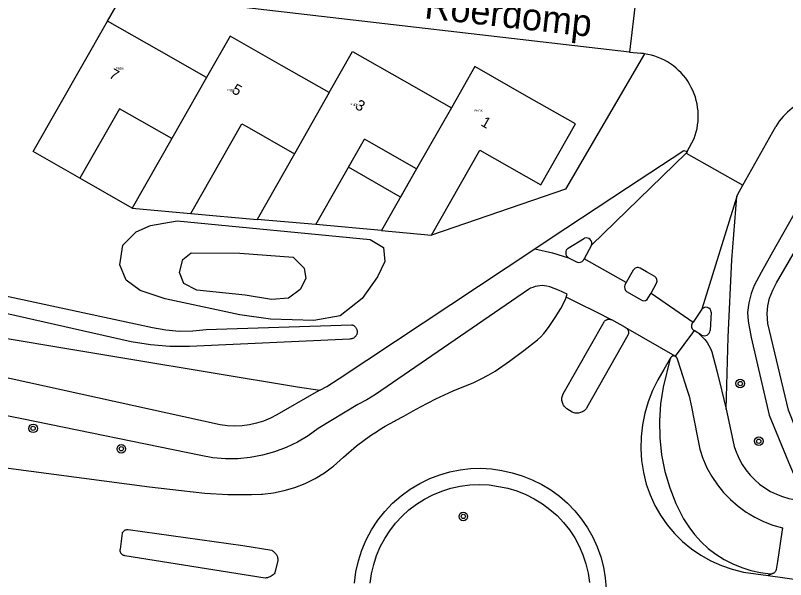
# Model space of a CAD drawing. Extents: x 131000 to 133013, y 393000 to 396501.
# Drawn here: x 131784.2 to 131855.9, y 393446.7 to 393499.2 of the extents above; entities that cross this region are included whole.
import ezdxf

# ---------------------------------------------------------------- set-up
doc = ezdxf.new("R2010")
doc.units = 0
for name, color, linetype in [('gg-anno-huisnummerreeks BGT', 7, 'Continuous'), ('gg-anno-openbare ruimte label', 7, 'Continuous'), ('gg-bbg-luifel en loopbrug', 7, 'Continuous'), ('gt-symb-boom', 7, 'Continuous'), ('gx-grn-maaiveld', 7, 'Continuous'), ('kenmerkpunt-x pandkandidaat', 7, 'Continuous')]:
    doc.layers.add(name, color=color, linetype=linetype)

# ---------------------------------------------------------------- blocks, each defined once
blk = doc.blocks.new('gt0-BOOM')
at = {"layer": 'gt-symb-boom'}
for radius in [0.4, 0.2]:
    blk.add_circle((0, 0), radius, dxfattribs=at)

msp = doc.modelspace()

# ---------------------------------------------------------------- linework, layer by layer
at = {"layer": 'gg-bbg-luifel en loopbrug'}
for points in [[(131821.568, 393484.913), (131820.064, 393482.286), (131815.225, 393485.055), (131816.72, 393487.688)], [(131821.568, 393484.913), (131817.165, 393487.433), (131816.72, 393487.688)]]:
    msp.add_lwpolyline(points, dxfattribs=at)
at = {"layer": 'gx-grn-maaiveld'}
for p, q in [((131792.797, 393498.663), (131796.255, 393504.69)), ((131841.965, 393500.754), (131841.4, 393495.785)), ((131841.4, 393495.785), (131842.451, 393495.664)), ((131802.004, 393493.4), (131798.771, 393487.723)), ((131813.42, 393492.003), (131810.189, 393486.311)), ((131824.81, 393490.6), (131821.568, 393484.913)), ((131851.927, 393483.389), (131855.005, 393488.868)), ((131798.771, 393487.723), (131795.089, 393481.255)), ((131812.196, 393479.719), (131816.72, 393487.688)), ((131846.751, 393486.521), (131847.401, 393487.729)), ((131810.189, 393486.311), (131806.726, 393480.21)), ((131837.862, 393477.802), (131846.664, 393486.362)), ((131846.751, 393486.521), (131846.664, 393486.362)), ((131846.664, 393486.362), (131851.927, 393483.389)), ((131821.568, 393484.913), (131818.296, 393479.171)), ((131795.089, 393481.255), (131790.202, 393484.039)), ((131851.389, 393482.329), (131848.128, 393471.843)), ((131795.089, 393481.255), (131800.562, 393480.764)), ((131800.562, 393480.764), (131806.726, 393480.21)), ((131812.196, 393479.719), (131806.726, 393480.21)), ((131818.296, 393479.171), (131812.196, 393479.719)), ((131818.296, 393479.171), (131822.954, 393478.752)), ((131835.671, 393477.544), (131837.198, 393478.456)), ((131837.862, 393477.802), (131837.181, 393476.535)), ((131835.722, 393476.63), (131836.462, 393476.246)), ((131837.103, 393476.415), (131837.181, 393476.535)), ((131841.08, 393474.329), (131837.181, 393476.535)), ((131841.733, 393475.473), (131841.08, 393474.329)), ((131841.08, 393474.329), (131840.961, 393474.106)), ((131843.406, 393473.334), (131843.915, 393474.278)), ((131842.506, 393472.683), (131841.151, 393473.465)), ((131843.141, 393472.901), (131843.406, 393473.334)), ((131843.406, 393473.334), (131847.306, 393470.653)), ((131848.128, 393471.843), (131847.306, 393470.653)), ((131848.994, 393471.579), (131848.894, 393469.87)), ((131845.634, 393467.474), (131841.061, 393470.11)), ((131847.306, 393470.653), (131847.231, 393470.538)), ((131847.352, 393469.89), (131847.409, 393469.855)), ((131848.106, 393469.432), (131847.847, 393469.589)), ((131854.627, 393447.213), (131854.308, 393447.064)), ((131854.308, 393447.064), (131857.986, 393446.55))]:
    msp.add_line(p, q, dxfattribs=at)
for points in [[(131841.4, 393495.785), (131805.488, 393499.915), (131803.793, 393500.125)], [(131790.202, 393484.039), (131785.863, 393486.524), (131792.797, 393498.663)], [(131802.004, 393493.4), (131797.595, 393495.921), (131792.797, 393498.663)], [(131813.42, 393492.003), (131809.004, 393494.518), (131804.198, 393497.254), (131802.004, 393493.4)], [(131813.42, 393492.003), (131815.594, 393495.832), (131820.403, 393493.102), (131824.81, 393490.6)], [(131842.779, 393495.625), (131835.424, 393483.025), (131822.954, 393478.752)], [(131822.954, 393478.752), (131827.466, 393486.635), (131833.13, 393483.41), (131836.362, 393489.086), (131831.803, 393491.689), (131826.997, 393494.438), (131824.81, 393490.6)], [(131862.924, 393491.661), (131854.702, 393477.147), (131853.632, 393475.269), (131852.984, 393474.065), (131852.72, 393473.311), (131852.495, 393472.451), (131852.362, 393471.538), (131852.442, 393470.731), (131852.73, 393469.199), (131854.397, 393461.992), (131856.191, 393457.626), (131856.644, 393456.535), (131856.829, 393456.033), (131856.935, 393455.252), (131856.961, 393454.71), (131856.894, 393454.118)], [(131798.771, 393487.723), (131793.898, 393490.509), (131790.202, 393484.039)], [(131800.562, 393480.764), (131805.311, 393489.103), (131805.758, 393488.847), (131810.189, 393486.311)], [(131832.575, 393477.466), (131834.011, 393478.417), (131841.205, 393483.174), (131846.434, 393486.632), (131846.751, 393486.521)], [(131858.644, 393453.895), (131858.734, 393454.829), (131858.721, 393455.596), (131858.588, 393456.416), (131858.207, 393457.354), (131857.847, 393458.261), (131856.836, 393460.807), (131856.188, 393462.439), (131854.257, 393470.522), (131854.191, 393471.462), (131854.27, 393472.176), (131854.429, 393472.89), (131854.733, 393473.605), (131855.073, 393474.304), (131858.909, 393480.918), (131860.759, 393484.12)], [(131851.389, 393482.329), (131851.462, 393482.562), (131851.927, 393483.389)], [(131850.393, 393462.558), (131850.571, 393469.26), (131850.924, 393476.456), (131851.389, 393482.329)], [(131807.967, 393470.905), (131805.106, 393471.337), (131798.169, 393472.808), (131795.822, 393473.576), (131794.528, 393474.565), (131793.953, 393475.982), (131794.217, 393477.803), (131795.455, 393479.064), (131796.804, 393479.624), (131799.273, 393480.068), (131817.236, 393478.33), (131818.478, 393477.588), (131818.609, 393476.299), (131817.941, 393474.849), (131816.487, 393472.854), (131814.453, 393471.22), (131811.987, 393470.796), (131807.967, 393470.905)], [(131812.562, 393464.3), (131813.215, 393464.649), (131814.373, 393465.406), (131832.575, 393477.466)], [(131832.575, 393477.466), (131834.23, 393477.081), (131835.722, 393476.63)], [(131800.581, 393477.106), (131805.11, 393477.068), (131810.065, 393476.684), (131811.097, 393475.671), (131811.253, 393474.693), (131810.716, 393473.674), (131809.636, 393472.872), (131808.062, 393472.74), (131805.617, 393473.155), (131801.109, 393473.627), (131799.897, 393474.234), (131799.504, 393475.276), (131799.795, 393476.459), (131800.581, 393477.106)], [(131843.741, 393474.877), (131842.976, 393475.319), (131842.37, 393475.669)], [(131779.934, 393473.811), (131796.968, 393470.137), (131798.21, 393469.915), (131799.468, 393469.809), (131800.73, 393469.821), (131801.985, 393469.95), (131815.501, 393470.407), (131815.557, 393470.393), (131815.612, 393470.373), (131815.665, 393470.349), (131815.716, 393470.32), (131815.764, 393470.288), (131815.809, 393470.251), (131815.85, 393470.21), (131815.888, 393470.166), (131815.922, 393470.119), (131815.952, 393470.07), (131815.978, 393470.017), (131815.999, 393469.963), (131816.015, 393469.907), (131816.026, 393469.85), (131816.032, 393469.793), (131816.034, 393469.734), (131816.03, 393469.676), (131816.022, 393469.619), (131816.008, 393469.562), (131815.99, 393469.507), (131815.967, 393469.454), (131815.939, 393469.403), (131815.907, 393469.354), (131815.871, 393469.308), (131815.832, 393469.266), (131815.788, 393469.227), (131815.742, 393469.192), (131815.693, 393469.161), (131815.641, 393469.135), (131815.587, 393469.113), (131815.532, 393469.096), (131815.475, 393469.083), (131815.417, 393469.076), (131815.359, 393469.073), (131800.414, 393468.372), (131798.595, 393468.377), (131796.781, 393468.521), (131794.983, 393468.803), (131779.726, 393472.268)], [(131835.489, 393472.975), (131835.571, 393473.261), (131834.792, 393473.629), (131833.982, 393473.924), (131833.697, 393473.998)], [(131831.981, 393473.682), (131817.738, 393463.913), (131816.938, 393463.406), (131816.096, 393462.971), (131812.404, 393460.759), (131811.466, 393460.076), (131810.471, 393459.479), (131809.427, 393458.974), (131808.342, 393458.563), (131807.225, 393458.25), (131806.084, 393458.038), (131804.929, 393457.929), (131803.769, 393457.922), (131802.613, 393458.02), (131801.47, 393458.219), (131784.823, 393461.63), (131781.36, 393462.34), (131757.983, 393467.134)], [(131821.238, 393462.374), (131821.945, 393462.75), (131822.654, 393463.122), (131823.364, 393463.491), (131824.984, 393464.244), (131826.906, 393465.031), (131827.581, 393465.352), (131828.244, 393465.699), (131828.891, 393466.073), (131830.229, 393467.012), (131831.54, 393467.99), (131832.821, 393469.005), (131833.126, 393469.279), (131833.408, 393469.576), (131833.666, 393469.894), (131833.899, 393470.231), (131834.473, 393471.061), (131834.989, 393471.927), (131835.446, 393472.826), (131835.489, 393472.975)], [(131839.707, 393470.865), (131838.314, 393471.562), (131836.542, 393472.448), (131835.489, 393472.975)], [(131766.909, 393471.889), (131770.67, 393471.257), (131777.288, 393470.154), (131794.768, 393467.239), (131810.475, 393464.62), (131812.562, 393464.3)], [(131841.061, 393470.11), (131841.097, 393470.084), (131841.131, 393470.055), (131841.162, 393470.023), (131841.19, 393469.988), (131841.215, 393469.952), (131841.237, 393469.913), (131841.255, 393469.872), (131841.27, 393469.83), (131841.281, 393469.787), (131841.289, 393469.743), (131841.292, 393469.699), (131841.292, 393469.654), (131841.288, 393469.61), (131841.28, 393469.566), (131841.268, 393469.523), (131841.253, 393469.481), (131841.234, 393469.441), (131837.43, 393462.697), (131837.376, 393462.616), (131837.314, 393462.539), (131837.246, 393462.469), (131837.172, 393462.404), (131837.092, 393462.347), (131837.008, 393462.297), (131836.92, 393462.254), (131836.828, 393462.22), (131836.733, 393462.194), (131836.637, 393462.177), (131836.539, 393462.168), (131836.441, 393462.168), (131836.343, 393462.176), (131836.247, 393462.194), (131836.152, 393462.22), (131836.06, 393462.254), (131835.569, 393462.587), (131835.495, 393462.64), (131835.426, 393462.7), (131835.362, 393462.765), (131835.304, 393462.836), (131835.252, 393462.911), (131835.207, 393462.991), (131835.169, 393463.074), (131835.138, 393463.16), (131835.115, 393463.249), (131835.1, 393463.339), (131835.093, 393463.43), (131835.093, 393463.521), (131835.102, 393463.612), (131835.118, 393463.702), (131835.142, 393463.79), (131835.173, 393463.876), (131835.212, 393463.959), (131839.039, 393470.682), (131839.067, 393470.72), (131839.099, 393470.755), (131839.133, 393470.787), (131839.17, 393470.816), (131839.21, 393470.842), (131839.251, 393470.864), (131839.295, 393470.882), (131839.339, 393470.896), (131839.385, 393470.907), (131839.432, 393470.913), (131839.479, 393470.915), (131839.526, 393470.913), (131839.573, 393470.907), (131839.619, 393470.897), (131839.664, 393470.883), (131839.707, 393470.865)], [(131841.061, 393470.11), (131841.046, 393470.119), (131841.031, 393470.128), (131841.016, 393470.136), (131839.735, 393470.851), (131839.726, 393470.856), (131839.717, 393470.861), (131839.707, 393470.865)], [(131847.409, 393469.855), (131847.257, 393469.651), (131845.634, 393467.474)], [(131847.847, 393469.589), (131847.759, 393469.643), (131847.409, 393469.855)], [(131847.847, 393469.589), (131848.194, 393469.257), (131848.41, 393469.013), (131848.605, 393468.751), (131848.777, 393468.474), (131848.924, 393468.183), (131849.047, 393467.881), (131849.515, 393466.112), (131849.964, 393464.337), (131850.393, 393462.558)], [(131812.562, 393464.3), (131811.995, 393463.996), (131808.565, 393462.003), (131807.957, 393461.692), (131807.324, 393461.434), (131806.671, 393461.232), (131806.003, 393461.087), (131805.325, 393461), (131804.642, 393460.972), (131803.96, 393461.003), (131803.282, 393461.092), (131780.397, 393466.1), (131765.925, 393469.048)], [(131845.185, 393467.244), (131844.593, 393466.222), (131844.015, 393465.272), (131843.521, 393464.274), (131843.117, 393463.238), (131842.804, 393462.17), (131842.586, 393461.079), (131842.464, 393459.973), (131842.438, 393458.861), (131842.51, 393457.751), (131842.678, 393456.651), (131842.941, 393455.57), (131843.298, 393454.563), (131843.743, 393453.593), (131844.274, 393452.667), (131844.887, 393451.792), (131845.575, 393450.976), (131846.334, 393450.225), (131847.158, 393449.545), (131848.04, 393448.943), (131848.972, 393448.421), (131849.947, 393447.987), (131850.958, 393447.641), (131851.995, 393447.388), (131854.308, 393447.064)], [(131845.185, 393467.244), (131844.537, 393464.591), (131844.285, 393463.03), (131844.173, 393461.452), (131844.203, 393459.87), (131844.373, 393458.298), (131844.683, 393456.747), (131845.13, 393455.229), (131845.71, 393453.758), (131846.419, 393452.344), (131846.902, 393451.581), (131847.449, 393450.864), (131848.058, 393450.198), (131848.722, 393449.587), (131849.438, 393449.038), (131850.199, 393448.553), (131851, 393448.137), (131851.834, 393447.793), (131852.695, 393447.523), (131853.577, 393447.33), (131854.472, 393447.215), (131854.511, 393447.21), (131854.549, 393447.208), (131854.588, 393447.209), (131854.627, 393447.213)], [(131845.634, 393467.474), (131845.607, 393467.484), (131845.581, 393467.492), (131845.553, 393467.498), (131845.526, 393467.501), (131845.498, 393467.502), (131845.47, 393467.5), (131845.443, 393467.496), (131845.416, 393467.49), (131845.39, 393467.482), (131845.365, 393467.472), (131845.341, 393467.459), (131845.317, 393467.445), (131845.296, 393467.428), (131845.275, 393467.41), (131845.257, 393467.39), (131845.24, 393467.368), (131845.224, 393467.346), (131845.211, 393467.322), (131845.2, 393467.297), (131845.192, 393467.271), (131845.185, 393467.244)], [(131845.634, 393467.474), (131845.658, 393467.461), (131845.664, 393467.458), (131845.689, 393467.441), (131845.712, 393467.423), (131845.733, 393467.403), (131845.752, 393467.381), (131845.769, 393467.358), (131845.784, 393467.333), (131845.796, 393467.307), (131845.819, 393467.236), (131846.136, 393466.263), (131846.741, 393464.41), (131846.952, 393463.761), (131847.148, 393462.767), (131847.681, 393460.058), (131847.925, 393458.819), (131848.225, 393457.941), (131848.28, 393457.819), (131848.602, 393457.093), (131849.05, 393456.28), (131849.569, 393455.511), (131850.152, 393454.789), (131850.552, 393454.375), (131850.797, 393454.121), (131851.497, 393453.513), (131852.248, 393452.968), (131852.519, 393452.805), (131853.044, 393452.49), (131853.879, 393452.084), (131854.746, 393451.753), (131855.638, 393451.499), (131855.577, 393451.101), (131855.162, 393448.373), (131855.075, 393447.805), (131855.047, 393447.621), (131855.037, 393447.577), (131855.024, 393447.535), (131855.007, 393447.494), (131854.986, 393447.454), (131854.961, 393447.417), (131854.934, 393447.382), (131854.903, 393447.349), (131854.87, 393447.319), (131854.834, 393447.293), (131854.796, 393447.27), (131854.754, 393447.249), (131854.714, 393447.234), (131854.671, 393447.221), (131854.627, 393447.213)], [(131756.831, 393460.594), (131796.708, 393455.324), (131799.679, 393454.977), (131801.839, 393454.728), (131804.01, 393454.605), (131806.184, 393454.608), (131807.119, 393454.638), (131807.213, 393454.642), (131808.235, 393454.763), (131809.244, 393454.97), (131810.23, 393455.263), (131811.189, 393455.639), (131812.112, 393456.096), (131812.992, 393456.629), (131813.752, 393457.183), (131813.824, 393457.235), (131814.76, 393458.083), (131815.982, 393459.13), (131817.275, 393460.088), (131817.922, 393460.501), (131818.085, 393460.605), (131818.631, 393460.953), (131819.497, 393461.432), (131819.596, 393461.485), (131820.366, 393461.906), (131821.238, 393462.374)], [(131850.393, 393462.558), (131850.994, 393459.659), (131851.143, 393459.065), (131851.342, 393458.487), (131851.403, 393458.351)], [(131851.403, 393458.351), (131851.592, 393457.928), (131851.889, 393457.393), (131852.231, 393456.886), (131852.617, 393456.411), (131853.042, 393455.971), (131853.505, 393455.57), (131854, 393455.21), (131854.525, 393454.896), (131855.075, 393454.628), (131855.647, 393454.409), (131856.235, 393454.241), (131856.894, 393454.118)], [(131815.785, 393446.364), (131815.923, 393447.405), (131816.153, 393448.429), (131816.475, 393449.428), (131816.884, 393450.395), (131817.379, 393451.321), (131817.955, 393452.199), (131818.607, 393453.022), (131819.33, 393453.783), (131820.118, 393454.477), (131820.965, 393455.097), (131821.865, 393455.638), (131822.809, 393456.097), (131823.721, 393456.446), (131824.659, 393456.717), (131825.617, 393456.906), (131826.587, 393457.014), (131827.563, 393457.039), (131828.537, 393456.981), (131829.503, 393456.84), (131830.454, 393456.618), (131831.405, 393456.338), (131832.328, 393455.977), (131833.218, 393455.538), (131834.066, 393455.024), (131834.867, 393454.44)], [(131817.255, 393446.355), (131817.378, 393447.224), (131817.575, 393448.079), (131817.846, 393448.914), (131818.188, 393449.722), (131818.599, 393450.498), (131819.075, 393451.235), (131819.613, 393451.929), (131820.209, 393452.573), (131820.858, 393453.163), (131821.556, 393453.695), (131822.298, 393454.165), (131823.077, 393454.569), (131823.904, 393454.917), (131824.758, 393455.189), (131825.634, 393455.383), (131826.523, 393455.498), (131827.42, 393455.532), (131828.315, 393455.486), (131829.203, 393455.36), (131830.068, 393455.182), (131830.914, 393454.93), (131831.734, 393454.605), (131832.524, 393454.209), (131833.276, 393453.746), (131833.984, 393453.22), (131834.644, 393452.634), (131835.251, 393451.992), (131835.799, 393451.3), (131836.285, 393450.563), (131836.705, 393449.787), (131837.056, 393448.977), (131837.335, 393448.139), (131837.54, 393447.281), (131837.669, 393446.407)], [(131834.867, 393454.44), (131835.615, 393453.789), (131836.304, 393453.077), (131836.93, 393452.308), (131837.488, 393451.488), (131837.973, 393450.624), (131838.382, 393449.721), (131838.713, 393448.786), (131838.962, 393447.826), (131839.128, 393446.849), (131839.21, 393445.861)], [(131794.412, 393448.906), (131794.37, 393448.911), (131794.329, 393448.92), (131794.289, 393448.932), (131794.25, 393448.948), (131794.213, 393448.967), (131794.178, 393448.989), (131794.144, 393449.015), (131794.113, 393449.043), (131794.085, 393449.074), (131794.06, 393449.108), (131794.037, 393449.143), (131794.018, 393449.18), (131794.002, 393449.219), (131793.99, 393449.259), (131793.982, 393449.3), (131793.977, 393449.342), (131793.975, 393449.384), (131793.978, 393449.426), (131793.984, 393449.467), (131793.994, 393449.508), (131794.177, 393451.018), (131794.195, 393451.059), (131794.217, 393451.099), (131794.242, 393451.136), (131794.27, 393451.171), (131794.302, 393451.203), (131794.336, 393451.232), (131794.372, 393451.258), (131794.411, 393451.281), (131794.451, 393451.3), (131794.493, 393451.316), (131794.537, 393451.328), (131794.581, 393451.336), (131794.625, 393451.34), (131794.67, 393451.34), (131794.715, 393451.336), (131805.378, 393449.86), (131808.077, 393449.405), (131808.152, 393449.367), (131808.223, 393449.323), (131808.289, 393449.273), (131808.352, 393449.217), (131808.409, 393449.156), (131808.461, 393449.091), (131808.507, 393449.021), (131808.547, 393448.948), (131808.581, 393448.871), (131808.608, 393448.792), (131808.628, 393448.711), (131808.641, 393448.628), (131808.646, 393448.545), (131808.645, 393448.461), (131808.384, 393447.307), (131808.303, 393447.22), (131808.214, 393447.139), (131808.12, 393447.066), (131808.019, 393447.002), (131807.914, 393446.946), (131807.804, 393446.898), (131807.691, 393446.86), (131807.575, 393446.832), (131807.457, 393446.813), (131794.412, 393448.906)]]:
    msp.add_lwpolyline(points, dxfattribs=at)
for centre, radius, start, end in [((131841.967, 393490.19), 5.495, 81.49688, 84.94157), ((131841.925, 393489.824), 5.863, 339.06456, 81.62141), ((131860.729, 393485.262), 6.765, 71.06498, 147.79011), ((131837.357, 393477.953), 0.527, 343.30285, 107.56656), ((131836.001, 393477.104), 0.55, 126.89528, 239.49215), ((131836.686, 393476.697), 0.503, 243.58077, 325.95915), ((131842.149, 393475.253), 0.471, 62.09027, 152.11518), ((131843.471, 393474.474), 0.485, 336.21554, 56.17995), ((131833.24, 393471.663), 2.379, 78.92109, 121.94706), ((131841.477, 393473.91), 0.552, 159.22284, 233.79806), ((131842.706, 393473.133), 0.493, 246.00814, 331.88728), ((131848.51, 393471.544), 0.485, 4.12966, 141.96267), ((131847.647, 393470.28), 0.49, 148.25367, 232.90021), ((131848.348, 393469.925), 0.549, 243.91069, 354.22321)]:
    msp.add_arc(centre, radius, start, end, dxfattribs=at)

# ---------------------------------------------------------------- block references
at = {"layer": 'gt-symb-boom'}
for p in [(131851.696, 393464.926), (131785.865, 393460.758), (131853.42, 393459.56), (131794.079, 393458.855), (131825.917, 393452.564)]:
    msp.add_blockref('gt0-BOOM', p, dxfattribs=at)

# ---------------------------------------------------------------- texts
at = {"layer": 'gg-anno-huisnummerreeks BGT'}
for s, rotation, p in [('7', 330.3, (131792.852, 393493.448)), ('5', 330.3, (131804.287, 393492.025)), ('3', 330.4, (131815.762, 393490.562)), ('1', 330.2, (131827.47, 393488.984))]:
    msp.add_text(s, height=1, rotation=rotation, dxfattribs=at).set_placement(p)
at = {"layer": 'gg-anno-openbare ruimte label'}
msp.add_text('Roerdomp', height=2.5, rotation=353.6, dxfattribs=at).set_placement((131822.231, 393498.933))
at = {"layer": 'kenmerkpunt-x pandkandidaat'}
for p in [(131793.563, 393494.151), (131803.884, 393492.136), (131815.397, 393490.772), (131826.958, 393490.222)]:
    msp.add_text('PNDK', height=0.2, dxfattribs=at).set_placement(p)

doc.saveas('drawing.dxf')
